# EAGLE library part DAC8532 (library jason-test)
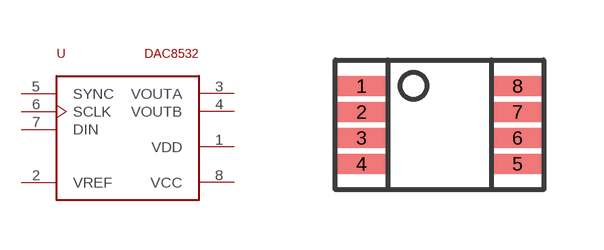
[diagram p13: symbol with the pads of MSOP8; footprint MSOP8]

Designator prefix -

## DAC8532  [MSOP8]
1  VDD  pwr
2  VREF
3  VOUTA  out
4  VOUTB  out
5  SYNC  in
6  SCLK  in
7  DIN  in
8  VCC  pwr

## Footprint MSOP8 (pad centres in mm)
smd 1.27 x 0.5: 1 -1.95,0.975; 2 -1.95,0.325; 3 -1.95,-0.325; 4 -1.95,-0.975; 5 1.95,-0.975; 6 1.95,-0.325; 7 1.95,0.325; 8 1.95,0.975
